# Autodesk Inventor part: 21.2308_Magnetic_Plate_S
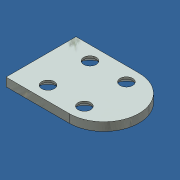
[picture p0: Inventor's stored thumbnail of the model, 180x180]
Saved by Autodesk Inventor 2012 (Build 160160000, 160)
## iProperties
Created: 2014-05
Part Number: 21.2308_Magnetic_Plate_S
Material: Steel
Document SubType Name: Modeling
Designer: Admin
Density: 7.85 g/cm^3
Mass: 15.9114 g
Surface Area: 19.368 cm^2
Volume: 2.02693 cm^3
Translation Standard: STEP AP214IS
FileName: 21.2308_Magnetic_Plate_S.STEP
PreProcessor: SolidWorks 2013
PostProcessor: Build: 160, Release: 2012 RTM - Date: Tue 03/01/2011
Sent Units: inch
Uncertainty: 1e-05
Author: Admin
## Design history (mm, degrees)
node "21.2308_Magnetic_Plate_S1"
node "Base1"
body "Solid1"
